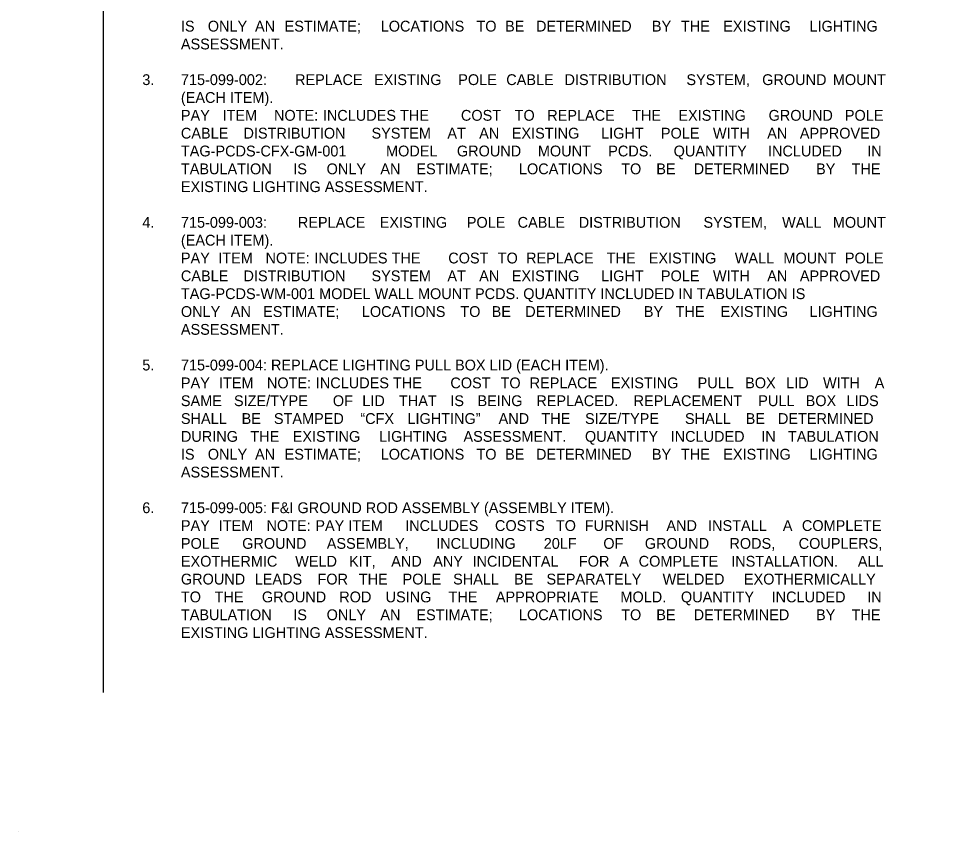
# Model space of a CAD drawing. Extents: x -55 to 2471539, y -90 to 3608906.
# Drawn here: x -55 to 549, y -90 to 436 of the extents above; entities that cross this region are included whole.
import ezdxf

# ---------------------------------------------------------------- set-up
doc = ezdxf.new("R2010")
doc.units = 0
for name, color, linetype in [('AdhocPoint_dp', 7, 'Continuous'), ('NonPlottingEle_dp', 7, 'Continuous'), ('TextNotes', 7, 'Continuous')]:
    doc.layers.add(name, color=color, linetype=linetype)

msp = doc.modelspace()

# ---------------------------------------------------------------- linework, layer by layer
at = {"layer": 'AdhocPoint_dp'}
msp.add_line((-55, -90), (-55, -90), dxfattribs=at)
at = {"layer": 'NonPlottingEle_dp'}
msp.add_lwpolyline([(0, 0), (0, 960), (1540, 960), (1540, 0)], dxfattribs=at)

# ---------------------------------------------------------------- texts
at = {"layer": 'TextNotes'}
for s, p in [('IS ', (50, 427.9)), ('ONLY ', (67.4, 427.9)), ('AN ', (97.97, 427.9)), ('ESTIMATE; ', (117.11, 427.9)), ('LOCATIONS ', (179.3, 427.9)), ('TO ', (241.27, 427.9)), ('BE ', (259.81, 427.9)), ('DETERMINED ', (279.81, 427.9)), ('BY ', (354.82, 427.9)), ('THE ', (373.62, 427.9)), ('EXISTING ', (400.99, 427.9)), ('LIGHTING ', (456.79, 427.9)), ('ASSESSMENT.', (50, 416.35)), ('3.', (25.02, 393.25)), ('715-099-002: ', (50, 393.25)), ('REPLACE ', (123.86, 393.25)), ('EXISTING ', (174.99, 393.25)), ('POLE ', (229.5, 393.25)), ('CABLE ', (260.56, 393.25)), ('DISTRIBUTION ', (298.26, 393.25)), ('SYSTEM, ', (377.15, 393.25)), ('GROUND ', (426.19, 393.25)), ('MOUNT ', (471.91, 393.25)), ('(EACH ITEM). ', (50, 381.7)), ('PAY ', (50, 370.15)), ('ITEM ', (76.93, 370.15)), ('NOTE:', (110.24, 370.15)), (' INCLUDES THE ', (139.28, 370.15)), ('COST ', (231.22, 370.15)), ('TO ', (265.98, 370.15)), ('REPLACE ', (287.09, 370.15)), ('THE ', (342, 370.15)), ('EXISTING ', (371.95, 370.15)), ('GROUND ', (430.33, 370.15)), ('POLE ', (479.69, 370.15)), ('CABLE ', (50, 358.6)), ('DISTRIBUTION ', (90.51, 358.6)), ('SYSTEM ', (173.36, 358.6)), ('AT ', (222.46, 358.6)), ('AN ', (243.02, 358.6)), ('EXISTING ', (264.14, 358.6)), ('LIGHT ', (321.94, 358.6)), ('POLE ', (360.64, 358.6)), ('WITH ', (394.33, 358.6)), ('AN ', (429.43, 358.6)), ('APPROVED ', (450.56, 358.6)), ('TAG-PCDS-CFX-GM-001 ', (50, 347.05)), ('MODEL ', (182.75, 347.05)), ('GROUND ', (228.62, 347.05)), ('MOUNT ', (281.02, 347.05)), ('PCDS. ', (326.54, 347.05)), ('QUANTITY ', (368.89, 347.05)), ('INCLUDED ', (429.94, 347.05)), ('IN ', (494.14, 347.05)), ('TABULATION ', (50, 335.5)), ('IS ', (122.73, 335.5)), ('ONLY ', (144.31, 335.5)), ('AN ', (179.07, 335.5)), ('ESTIMATE; ', (202.4, 335.5)), ('LOCATIONS ', (268.78, 335.5)), ('TO ', (334.94, 335.5)), ('BE ', (357.66, 335.5)), ('DETERMINED ', (381.85, 335.5)), ('BY ', (461.04, 335.5)), ('THE ', (484.03, 335.5)), ('EXISTING LIGHTING ASSESSMENT.', (50, 323.95)), ('4.', (25.02, 300.85)), ('715-099-003: ', (50, 300.85)), ('REPLACE ', (125.7, 300.85)), ('EXISTING ', (178.66, 300.85)), ('POLE ', (235.02, 300.85)), ('CABLE ', (267.92, 300.85)), ('DISTRIBUTION ', (307.45, 300.85)), ('SYSTEM, ', (388.19, 300.85)), ('WALL ', (439.06, 300.85)), ('MOUNT ', (471.91, 300.85)), ('(EACH ITEM).', (50, 289.3)), ('PAY ', (50, 277.75)), ('ITEM ', (74.19, 277.75)), ('NOTE:', (104.77, 277.75)), (' INCLUDES THE ', (133.8, 277.75)), ('COST ', (223.02, 277.75)), ('TO ', (255.03, 277.75)), ('REPLACE ', (273.41, 277.75)), ('THE ', (325.58, 277.75)), ('EXISTING ', (352.79, 277.75)), ('WALL ', (408.44, 277.75)), ('MOUNT ', (439.94, 277.75)), ('POLE ', (479.69, 277.75)), ('CABLE ', (50, 266.2)), ('DISTRIBUTION ', (90.51, 266.2)), ('SYSTEM ', (173.36, 266.2)), ('AT ', (222.46, 266.2)), ('AN ', (243.02, 266.2)), ('EXISTING ', (264.14, 266.2)), ('LIGHT ', (321.94, 266.2)), ('POLE ', (360.64, 266.2)), ('WITH ', (394.33, 266.2)), ('AN ', (429.43, 266.2)), ('APPROVED ', (450.56, 266.2)), ('TAG-PCDS-WM-001 MODEL WALL MOUNT PCDS. QUANTITY INCLUDED IN TABULATION IS ', (50, 254.65)), ('ONLY ', (50, 243.1)), ('AN ', (82.31, 243.1)), ('ESTIMATE; ', (103.2, 243.1)), ('LOCATIONS ', (167.12, 243.1)), ('TO ', (230.84, 243.1)), ('BE ', (251.11, 243.1)), ('DETERMINED ', (272.85, 243.1)), ('BY ', (349.6, 243.1)), ('THE ', (370.14, 243.1)), ('EXISTING ', (399.25, 243.1)), ('LIGHTING ', (456.79, 243.1)), ('ASSESSMENT.', (50, 231.55)), ('5.', (25.02, 208.45)), ('715-099-004: REPLACE LIGHTING PULL BOX LID (EACH ITEM).', (50, 208.45)), ('PAY ', (50, 196.9)), ('ITEM ', (74.65, 196.9)), ('NOTE:', (105.67, 196.9)), (' INCLUDES THE ', (134.71, 196.9)), ('COST ', (224.38, 196.9)), ('TO ', (256.85, 196.9)), ('REPLACE ', (275.68, 196.9)), ('EXISTING ', (328.3, 196.9)), ('PULL ', (384.41, 196.9)), ('BOX ', (415.16, 196.9)), ('LID ', (441.72, 196.9)), ('WITH ', (465.57, 196.9)), ('A ', (498.99, 196.9)), ('SAME ', (50, 185.35)), ('SIZE/TYPE ', (84.33, 185.35)), ('OF ', (148.33, 185.35)), ('LID ', (167.4, 185.35)), ('THAT ', (191.14, 185.35)), ('IS ', (224.35, 185.35)), ('BEING ', (241.94, 185.35)), ('REPLACED. ', (280.01, 185.35)), ('REPLACEMENT ', (342.97, 185.35)), ('PULL ', (423.66, 185.35)), ('BOX ', (454.31, 185.35)), ('LIDS ', (480.76, 185.35)), ('SIZE/TYPE ', (311.53, 173.8)), ('SHALL ', (50, 173.8)), ('BE ', (89.31, 173.8)), ('STAMPED ', (110.18, 173.8)), ('“CFX ', (166.12, 173.8)), ('LIGHTING” ', (196.61, 173.8)), ('AND ', (255.6, 173.8)), ('THE ', (283.3, 173.8)), ('SHALL ', (376.2, 173.8)), ('BE ', (415.51, 173.8)), ('DETERMINED ', (436.38, 173.8)), ('DURING ', (50, 162.25)), ('THE ', (94.97, 162.25)), ('EXISTING ', (122.38, 162.25)), ('LIGHTING ', (178.22, 162.25)), ('ASSESSMENT. ', (232.86, 162.25)), ('QUANTITY ', (311.48, 162.25)), ('INCLUDED ', (366.94, 162.25)), ('IN ', (425.56, 162.25)), ('TABULATION ', (442.86, 162.25)), ('IS ', (50, 150.7)), ('ONLY ', (67.4, 150.7)), ('AN ', (97.97, 150.7)), ('ESTIMATE; ', (117.11, 150.7)), ('LOCATIONS ', (179.3, 150.7)), ('TO ', (241.27, 150.7)), ('BE ', (259.81, 150.7)), ('DETERMINED ', (279.81, 150.7)), ('BY ', (354.82, 150.7)), ('THE ', (373.62, 150.7)), ('EXISTING ', (400.99, 150.7)), ('LIGHTING ', (456.79, 150.7)), ('ASSESSMENT.', (50, 139.15)), ('6.', (25.02, 116.05)), ('715-099-005: F&I GROUND ROD ASSEMBLY (ASSEMBLY ITEM).', (50, 116.05)), ('PAY ', (50, 104.5)), ('ITEM ', (74.5, 104.5)), ('NOTE:', (105.37, 104.5)), (' PAY ITEM ', (134.41, 104.5)), ('INCLUDES ', (195.14, 104.5)), ('COSTS ', (253.26, 104.5)), ('TO ', (292.66, 104.5)), ('FURNISH ', (311.34, 104.5)), ('AND ', (364.2, 104.5)), ('INSTALL ', (391.17, 104.5)), ('A ', (439.54, 104.5)), ('COMPLETE ', (451.89, 104.5)), ('POLE ', (50, 92.95)), ('GROUND ', (89.67, 92.95)), ('ASSEMBLY, ', (144.41, 92.95)), ('INCLUDING ', (215.21, 92.95)), ('20LF ', (284.81, 92.95)), ('OF ', (323.39, 92.95)), ('GROUND ', (350.23, 92.95)), ('RODS, ', (404.97, 92.95)), ('COUPLERS, ', (449.79, 92.95)), ('EXOTHERMIC ', (50, 81.4)), ('WELD ', (123.96, 81.4)), ('KIT, ', (158.84, 81.4)), ('AND ', (186.11, 81.4)), ('ANY ', (213.3, 81.4)), ('INCIDENTAL ', (238.74, 81.4)), ('FOR ', (307.56, 81.4)), ('A ', (333.68, 81.4)), ('COMPLETE ', (346.25, 81.4)), ('INSTALLATION. ', (406.12, 81.4)), ('ALL ', (488.09, 81.4)), ('GROUND ', (50, 69.85)), ('LEADS ', (97.76, 69.85)), ('FOR ', (138.39, 69.85)), ('THE ', (165.13, 69.85)), ('POLE ', (193.48, 69.85)), ('SHALL ', (226.17, 69.85)), ('BE ', (265.6, 69.85)), ('SEPARATELY ', (286.59, 69.85)), (' WELDED ', (359.13, 69.85)), ('EXOTHERMICALLY ', (414.36, 69.85)), ('TO ', (50, 58.3)), ('THE ', (71.8, 58.3)), ('GROUND ', (102.43, 58.3)), ('ROD ', (152.48, 58.3)), ('USING ', (182.46, 58.3)), ('THE ', (223.18, 58.3)), ('APPROPRIATE ', (253.81, 58.3)), ('MOLD. ', (334.45, 58.3)), ('QUANTITY ', (373.6, 58.3)), ('INCLUDED ', (432.29, 58.3)), ('IN ', (494.14, 58.3)), ('TABULATION ', (50, 46.75)), ('IS ', (122.73, 46.75)), ('ONLY ', (144.31, 46.75)), ('AN ', (179.07, 46.75)), ('ESTIMATE; ', (202.4, 46.75)), ('LOCATIONS ', (268.78, 46.75)), ('TO ', (334.94, 46.75)), ('BE ', (357.66, 46.75)), ('DETERMINED ', (381.85, 46.75)), ('BY ', (461.04, 46.75)), ('THE ', (484.03, 46.75)), ('EXISTING LIGHTING ASSESSMENT.', (50, 35.2))]:
    msp.add_text(s, height=7, dxfattribs=at).set_placement(p)

doc.saveas('drawing.dxf')
